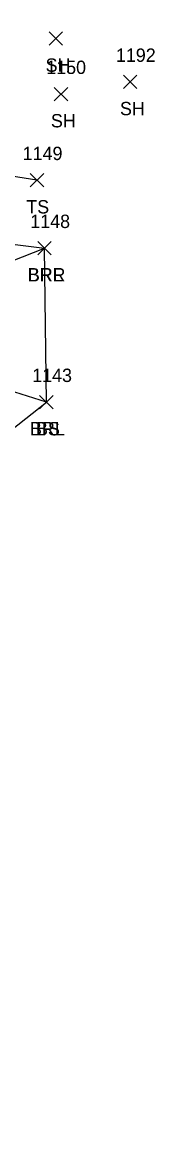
# Model space of a CAD drawing. Extents: x 1554917 to 1555870, y 813367 to 816333.
# Drawn here: x 1555102.6 to 1555122.4, y 813420.9 to 813586.9 of the extents above; entities that cross this region are included whole.
import ezdxf

# ---------------------------------------------------------------- set-up
doc = ezdxf.new("R2010")
doc.units = 0
for name, color, linetype in [('L_A', 7, 'Continuous'), ('L_I', 7, 'Continuous'), ('L_TIC', 7, 'Continuous'), ('LABL', 7, 'Continuous'), ('LELB', 7, 'Continuous')]:
    doc.layers.add(name, color=color, linetype=linetype)

msp = doc.modelspace()

# ---------------------------------------------------------------- linework, layer by layer
at = {"layer": 'L_TIC'}
for points in [[(1555106.63, 813583.42), (1555108.63, 813585.42)], [(1555108.63, 813583.42), (1555106.63, 813585.42)], [(1555117.74, 813576.91), (1555119.74, 813578.91)], [(1555119.74, 813576.91), (1555117.74, 813578.91)], [(1555107.42, 813575.09), (1555109.42, 813577.09)], [(1555109.42, 813575.09), (1555107.42, 813577.09)], [(1555103.83, 813562.19), (1555105.83, 813564.19)], [(1555105.83, 813562.19), (1555103.83, 813564.19)], [(1555104.94, 813552.01), (1555106.94, 813554.01)], [(1555106.94, 813552.01), (1555104.94, 813554.01)], [(1555104.94, 813552.01), (1555106.94, 813554.01)], [(1555106.94, 813552.01), (1555104.94, 813554.01)], [(1555105.23, 813528.94), (1555107.23, 813530.94)], [(1555107.23, 813528.94), (1555105.23, 813530.94)], [(1555105.23, 813528.94), (1555107.23, 813530.94)], [(1555107.23, 813528.94), (1555105.23, 813530.94)]]:
    msp.add_lwpolyline(points, dxfattribs=at)
at = {"layer": 'LABL'}
for points in [[(1555021.43, 813420.92), (1555042.06, 813475.32), (1555060.32, 813524.58), (1555067.05, 813522.89), (1555076.12, 813521.23), (1555083.3, 813530.48), (1555085.29, 813534.37), (1555089.23, 813546.42), (1555105.94, 813553.01)], [(1555021.43, 813420.92), (1555032.42, 813420.89), (1555053.86, 813467), (1555085.28, 813513.33), (1555106.23, 813529.94), (1555105.94, 813553.01)]]:
    msp.add_lwpolyline(points, dxfattribs=at)
at = {"layer": 'LELB'}
for points in [[(1555104.83, 813563.19), (1555089.64, 813565.56), (1555077.66, 813559.05), (1555084.43, 813577.98), (1555091.02, 813589.64), (1555101.22, 813603.84)], [(1555092.42, 813554.68), (1555105.94, 813553.01)], [(1555106.23, 813529.94), (1555098.61, 813532.31), (1555085.29, 813534.37), (1555078.48, 813536.1), (1555067.83, 813537.87)]]:
    msp.add_lwpolyline(points, dxfattribs=at)

# ---------------------------------------------------------------- texts
at = {"layer": 'L_A'}
for s, p in [('SH', (1555106.12, 813579.42)), ('SH', (1555117.23, 813572.91)), ('SH', (1555106.91, 813571.09)), ('TS', (1555103.23, 813558.19)), ('BRR', (1555103.43, 813548.01)), ('BRL', (1555103.48, 813548.01)), ('BRL', (1555103.78, 813524.94)), ('BS', (1555104.68, 813524.94))]:
    msp.add_text(s, height=2, dxfattribs=at).set_placement(p)
at = {"layer": 'L_I'}
for s, p in [('1192', (1555116.62, 813580.91)), ('1150', (1555106.21, 813579.09)), ('1149', (1555102.69, 813566.19)), ('1148', (1555103.82, 813556.01)), ('1148', (1555103.82, 813556.01)), ('1143', (1555104.11, 813532.94)), ('1143', (1555104.11, 813532.94))]:
    msp.add_text(s, height=2, dxfattribs=at).set_placement(p)

doc.saveas('drawing.dxf')
